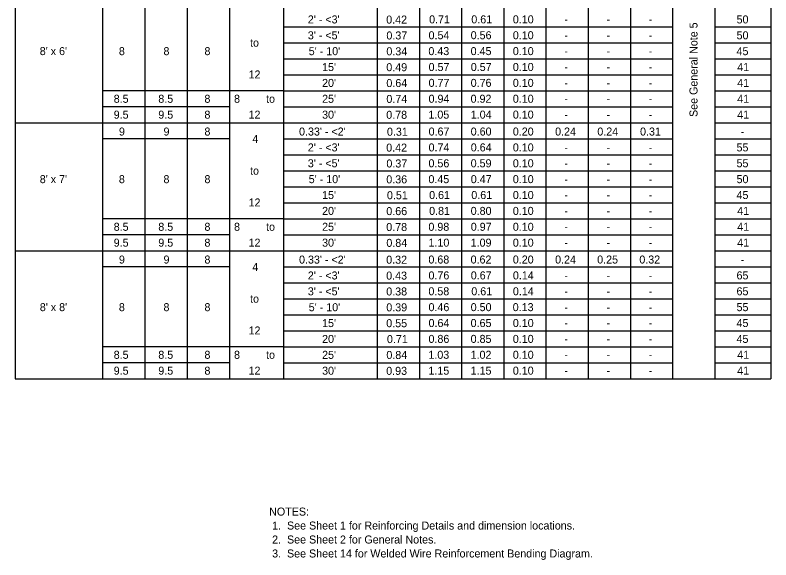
# Model space of a CAD drawing. Extents: x 10342.77 to 10344.98, y 76399.47 to 76400.59.
# Drawn here: x 10343.418 to 10344.012, y 76399.783 to 76400.212 of the extents above; entities that cross this region are included whole.
import ezdxf

# ---------------------------------------------------------------- set-up
doc = ezdxf.new("R2010")
doc.units = 0
doc.layers.add('AdhocPoint_dp', color=7, linetype='Continuous')
doc.layers.add('PlotBorder_dp', color=7, linetype='Continuous')

msp = doc.modelspace()

# ---------------------------------------------------------------- linework, layer by layer
at = {"layer": 'PlotBorder_dp'}
for p, q in [((10343.41763, 76400.49971), (10343.41763, 76399.92549)), ((10344.01237, 76400.49971), (10344.01237, 76399.92549)), ((10343.48627, 76400.47984), (10343.48627, 76399.92549)), ((10343.62871, 76400.47984), (10343.62871, 76399.92549)), ((10343.70259, 76400.47984), (10343.70259, 76399.92549)), ((10343.96818, 76400.47984), (10343.96818, 76399.92549)), ((10343.51963, 76400.46724), (10343.51963, 76399.92549)), ((10343.55299, 76400.46724), (10343.55299, 76399.92549)), ((10343.58635, 76400.46724), (10343.58635, 76399.92549)), ((10343.73579, 76400.44209), (10343.73579, 76399.92549)), ((10343.76899, 76400.44209), (10343.76899, 76399.92549)), ((10343.80219, 76400.44209), (10343.80219, 76399.92549)), ((10343.83539, 76400.44209), (10343.83539, 76399.92549)), ((10343.86859, 76400.44209), (10343.86859, 76399.92549)), ((10343.86859, 76400.44209), (10343.86859, 76399.92549)), ((10343.90178, 76400.44209), (10343.90178, 76399.92549)), ((10343.93498, 76400.44209), (10343.93498, 76399.92549)), ((10343.62871, 76400.20269), (10343.93498, 76400.20269)), ((10343.96818, 76400.20269), (10344.01237, 76400.20269)), ((10343.62871, 76400.19009), (10343.93498, 76400.19009)), ((10343.96818, 76400.19009), (10344.01237, 76400.19009)), ((10343.62871, 76400.17749), (10343.93498, 76400.17749)), ((10343.96818, 76400.17749), (10344.01237, 76400.17749)), ((10343.62871, 76400.16489), (10343.93498, 76400.16489)), ((10343.96818, 76400.16489), (10344.01237, 76400.16489)), ((10343.62871, 76400.15229), (10343.48627, 76400.15229)), ((10343.62871, 76400.15229), (10343.93498, 76400.15229)), ((10343.96818, 76400.15229), (10344.01237, 76400.15229)), ((10343.58635, 76400.13969), (10343.48627, 76400.13969)), ((10343.62871, 76400.13969), (10343.93498, 76400.13969)), ((10343.96818, 76400.13969), (10344.01237, 76400.13969)), ((10343.41763, 76400.12709), (10343.93498, 76400.12709)), ((10343.62931, 76400.12709), (10343.70148, 76400.12709)), ((10343.96818, 76400.12709), (10344.01237, 76400.12709)), ((10343.58635, 76400.11449), (10343.48627, 76400.11449)), ((10343.62871, 76400.11449), (10343.93498, 76400.11449)), ((10343.96818, 76400.11449), (10344.01237, 76400.11449)), ((10343.62871, 76400.10189), (10343.93498, 76400.10189)), ((10343.96818, 76400.10189), (10344.01237, 76400.10189)), ((10343.62871, 76400.08929), (10343.93498, 76400.08929)), ((10343.96818, 76400.08929), (10344.01237, 76400.08929)), ((10343.62871, 76400.07669), (10343.93498, 76400.07669)), ((10343.96818, 76400.07669), (10344.01237, 76400.07669)), ((10343.62871, 76400.06409), (10343.93498, 76400.06409)), ((10343.96818, 76400.06409), (10344.01237, 76400.06409)), ((10343.62871, 76400.05149), (10343.48627, 76400.05149)), ((10343.62871, 76400.05149), (10343.93498, 76400.05149)), ((10343.96818, 76400.05149), (10344.01237, 76400.05149)), ((10343.58635, 76400.03889), (10343.48627, 76400.03889)), ((10343.62871, 76400.03889), (10343.93498, 76400.03889)), ((10343.96818, 76400.03889), (10344.01237, 76400.03889)), ((10343.41763, 76400.02629), (10343.93498, 76400.02629)), ((10343.62931, 76400.02629), (10343.70148, 76400.02629)), ((10343.96818, 76400.02629), (10344.01237, 76400.02629)), ((10343.58635, 76400.01369), (10343.48627, 76400.01369)), ((10343.62871, 76400.01369), (10343.93498, 76400.01369)), ((10343.96818, 76400.01369), (10344.01237, 76400.01369)), ((10343.62871, 76400.00109), (10343.93498, 76400.00109)), ((10343.96818, 76400.00109), (10344.01237, 76400.00109)), ((10343.62871, 76399.98849), (10343.93498, 76399.98849)), ((10343.96818, 76399.98849), (10344.01237, 76399.98849)), ((10343.62871, 76399.97589), (10343.93498, 76399.97589)), ((10343.96818, 76399.97589), (10344.01237, 76399.97589)), ((10343.62871, 76399.96329), (10343.93498, 76399.96329)), ((10343.96818, 76399.96329), (10344.01237, 76399.96329)), ((10343.62871, 76399.95069), (10343.48627, 76399.95069)), ((10343.62871, 76399.95069), (10343.93498, 76399.95069)), ((10343.96818, 76399.95069), (10344.01237, 76399.95069)), ((10343.58635, 76399.93809), (10343.48627, 76399.93809)), ((10343.62871, 76399.93809), (10343.93498, 76399.93809)), ((10343.62931, 76399.93809), (10343.70148, 76399.93809)), ((10343.96818, 76399.93809), (10344.01237, 76399.93809)), ((10343.41763, 76399.92549), (10344.01237, 76399.92549))]:
    msp.add_line(p, q, dxfattribs=at)

# ---------------------------------------------------------------- texts
at = {"layer": 'AdhocPoint_dp'}
msp.add_text('See General Note 5', height=0.0063, rotation=90, dxfattribs=at).set_placement((10343.95463, 76400.13159))
at = {"layer": 'PlotBorder_dp'}
for s, p in [("2' - <3'", (10343.64797, 76400.20526)), ('0.42', (10343.70967, 76400.20515)), ('0.71', (10343.74343, 76400.20531)), ('0.61', (10343.77663, 76400.20531)), ('0.10', (10343.8093, 76400.20531)), ('50', (10343.98538, 76400.20526)), ('-', (10343.84986, 76400.20531)), ('-', (10343.88307, 76400.20531)), ('-', (10343.91625, 76400.20531)), ("3' - <5'", (10343.64797, 76400.19276)), ('0.37', (10343.70981, 76400.19265)), ('0.54', (10343.74299, 76400.19281)), ('0.56', (10343.77613, 76400.19281)), ('0.10', (10343.8093, 76400.19281)), ('50', (10343.98538, 76400.19276)), ('to', (10343.60251, 76400.18692)), ('-', (10343.84986, 76400.19281)), ('-', (10343.88307, 76400.19281)), ('-', (10343.91625, 76400.19281)), ("8' x 6'", (10343.43702, 76400.18031)), ('8', (10343.49929, 76400.18027)), ('8', (10343.53438, 76400.18027)), ('8', (10343.56662, 76400.18027)), ("5' - 10'", (10343.64868, 76400.18026)), ('0.34', (10343.70979, 76400.18015)), ('0.43', (10343.74286, 76400.18031)), ('0.45', (10343.77609, 76400.18031)), ('0.10', (10343.8093, 76400.18031)), ('45', (10343.98533, 76400.18026)), ('-', (10343.84986, 76400.18031)), ('-', (10343.88307, 76400.18031)), ('-', (10343.91625, 76400.18031)), ("15'", (10343.6592, 76400.16776)), ('0.49', (10343.70973, 76400.16765)), ('0.57', (10343.74301, 76400.16781)), ('0.57', (10343.77621, 76400.16781)), ('0.10', (10343.8093, 76400.16781)), ('41', (10343.98587, 76400.16776)), ('12', (10343.60134, 76400.16192)), ('-', (10343.84986, 76400.16781)), ('-', (10343.88307, 76400.16781)), ('-', (10343.91625, 76400.16781)), ("20'", (10343.6592, 76400.15526)), ('0.64', (10343.70979, 76400.15515)), ('0.77', (10343.74301, 76400.15531)), ('0.76', (10343.77613, 76400.15531)), ('0.10', (10343.8093, 76400.15531)), ('41', (10343.98587, 76400.15526)), ('-', (10343.84986, 76400.15531)), ('-', (10343.88307, 76400.15531)), ('-', (10343.91625, 76400.15531)), ('8.5', (10343.49522, 76400.14277)), ('8.5', (10343.53032, 76400.14277)), ('8', (10343.56662, 76400.14277)), ('8 ', (10343.58991, 76400.14277)), ('to', (10343.61511, 76400.14277)), ("25'", (10343.6592, 76400.14276)), ('0.74', (10343.70979, 76400.14265)), ('0.94', (10343.74299, 76400.14281)), ('0.92', (10343.77607, 76400.14281)), ('0.10', (10343.8093, 76400.14281)), ('-', (10343.84986, 76400.14281)), ('-', (10343.88307, 76400.14281)), ('-', (10343.91625, 76400.14281)), ('41', (10343.98587, 76400.14276)), ('9.5', (10343.49522, 76400.13027)), ('9.5', (10343.53032, 76400.13027)), ('8', (10343.56662, 76400.13027)), ('12', (10343.60134, 76400.13027)), ("30'", (10343.6592, 76400.13026)), ('0.78', (10343.70969, 76400.13015)), ('1.05', (10343.74289, 76400.13031)), ('1.04', (10343.77619, 76400.13031)), ('0.10', (10343.8093, 76400.13031)), ('-', (10343.84986, 76400.13031)), ('-', (10343.88307, 76400.13031)), ('-', (10343.91625, 76400.13031)), ('41', (10343.98587, 76400.13026)), ('9', (10343.49933, 76400.11697)), ('9', (10343.53443, 76400.11697)), ('8', (10343.56662, 76400.11697)), ("0.33' - <2'", (10343.64107, 76400.11698)), ('0.31', (10343.71024, 76400.11682)), ('0.67', (10343.74301, 76400.11698)), ('0.60', (10343.77615, 76400.11698)), ('0.20', (10343.8093, 76400.11698)), ('0.24', (10343.84258, 76400.11698)), ('0.24', (10343.87579, 76400.11698)), ('0.31', (10343.90942, 76400.11698)), ('4', (10343.60429, 76400.11112)), ('-', (10343.98864, 76400.11698)), ("2' - <3'", (10343.64797, 76400.10448)), ('0.42', (10343.70967, 76400.10432)), ('0.74', (10343.74299, 76400.10448)), ('0.64', (10343.77619, 76400.10448)), ('0.10', (10343.8093, 76400.10448)), ('55', (10343.98533, 76400.10448)), ('-', (10343.84986, 76400.10448)), ('-', (10343.88307, 76400.10448)), ('-', (10343.91625, 76400.10448)), ("3' - <5'", (10343.64797, 76400.09198)), ('0.37', (10343.70981, 76400.09182)), ('0.56', (10343.74293, 76400.09198)), ('0.59', (10343.77613, 76400.09198)), ('0.10', (10343.8093, 76400.09198)), ('55', (10343.98533, 76400.09198)), ('to', (10343.60251, 76400.08612)), ('-', (10343.84986, 76400.09198)), ('-', (10343.88307, 76400.09198)), ('-', (10343.91625, 76400.09198)), ("8' x 7'", (10343.43702, 76400.07948)), ('8', (10343.49929, 76400.07947)), ('8', (10343.53438, 76400.07947)), ('8', (10343.56662, 76400.07947)), ("5' - 10'", (10343.64868, 76400.07948)), ('0.36', (10343.70973, 76400.07932)), ('0.45', (10343.74289, 76400.07948)), ('0.47', (10343.77621, 76400.07948)), ('0.10', (10343.8093, 76400.07948)), ('50', (10343.98538, 76400.07948)), ('-', (10343.84986, 76400.07948)), ('-', (10343.88307, 76400.07948)), ('-', (10343.91625, 76400.07948)), ("15'", (10343.6592, 76400.06698)), ('0.51', (10343.71024, 76400.06682)), ('0.61', (10343.74343, 76400.06698)), ('0.61', (10343.77663, 76400.06698)), ('0.10', (10343.8093, 76400.06698)), ('45', (10343.98533, 76400.06698)), ('12', (10343.60134, 76400.06112)), ('-', (10343.84986, 76400.06698)), ('-', (10343.88307, 76400.06698)), ('-', (10343.91625, 76400.06698)), ("20'", (10343.6592, 76400.05448)), ('0.66', (10343.70973, 76400.05432)), ('0.81', (10343.74343, 76400.05448)), ('0.80', (10343.77615, 76400.05448)), ('0.10', (10343.8093, 76400.05448)), ('41', (10343.98587, 76400.05448)), ('-', (10343.84986, 76400.05448)), ('-', (10343.88307, 76400.05448)), ('-', (10343.91625, 76400.05448)), ('8.5', (10343.49522, 76400.04197)), ('8.5', (10343.53032, 76400.04197)), ('8', (10343.56662, 76400.04197)), ('8 ', (10343.58991, 76400.04197)), ('to', (10343.61511, 76400.04197)), ("25'", (10343.6592, 76400.04198)), ('0.78', (10343.70969, 76400.04182)), ('0.98', (10343.74288, 76400.04198)), ('0.97', (10343.77621, 76400.04198)), ('0.10', (10343.8093, 76400.04198)), ('-', (10343.84986, 76400.04198)), ('-', (10343.88307, 76400.04198)), ('-', (10343.91625, 76400.04198)), ('41', (10343.98587, 76400.04198)), ('9.5', (10343.49522, 76400.02947)), ('9.5', (10343.53032, 76400.02947)), ('8', (10343.56662, 76400.02947)), ('12', (10343.60134, 76400.02947)), ("30'", (10343.6592, 76400.02948)), ('0.84', (10343.70979, 76400.02932)), ('1.10', (10343.74294, 76400.02948)), ('1.09', (10343.77613, 76400.02948)), ('0.10', (10343.8093, 76400.02948)), ('-', (10343.84986, 76400.02948)), ('-', (10343.88307, 76400.02948)), ('-', (10343.91625, 76400.02948)), ('41', (10343.98587, 76400.02948)), ('9', (10343.49933, 76400.01617)), ('9', (10343.53443, 76400.01617)), ('8', (10343.56662, 76400.01617)), ("0.33' - <2'", (10343.64107, 76400.01614)), ('0.32', (10343.70967, 76400.01604)), ('0.68', (10343.74288, 76400.01619)), ('0.62', (10343.77607, 76400.01619)), ('0.20', (10343.8093, 76400.01619)), ('0.24', (10343.84258, 76400.01619)), ('0.25', (10343.87569, 76400.01619)), ('0.32', (10343.90885, 76400.01619)), ('-', (10343.98864, 76400.01619)), ('4', (10343.60429, 76400.01032)), ("2' - <3'", (10343.64797, 76400.00364)), ('0.43', (10343.70966, 76400.00354)), ('0.76', (10343.74293, 76400.00369)), ('0.67', (10343.77621, 76400.00369)), ('0.14', (10343.80935, 76400.00369)), ('65', (10343.98533, 76400.00369)), ('-', (10343.84986, 76400.00369)), ('-', (10343.88307, 76400.00369)), ('-', (10343.91625, 76400.00369)), ("3' - <5'", (10343.64797, 76399.99114)), ('0.38', (10343.70969, 76399.99104)), ('0.58', (10343.74288, 76399.99119)), ('0.61', (10343.77663, 76399.99119)), ('0.14', (10343.80935, 76399.99119)), ('65', (10343.98533, 76399.99119)), ('to', (10343.60251, 76399.98532)), ('-', (10343.84986, 76399.99119)), ('-', (10343.88307, 76399.99119)), ('-', (10343.91625, 76399.99119)), ("8' x 8'", (10343.43707, 76399.97869)), ('8', (10343.49929, 76399.97867)), ('8', (10343.53438, 76399.97867)), ('8', (10343.56662, 76399.97867)), ("5' - 10'", (10343.64868, 76399.97864)), ('0.39', (10343.70973, 76399.97854)), ('0.46', (10343.74293, 76399.97869)), ('0.50', (10343.77615, 76399.97869)), ('0.13', (10343.80922, 76399.97869)), ('55', (10343.98533, 76399.97869)), ('-', (10343.84986, 76399.97869)), ('-', (10343.88307, 76399.97869)), ('-', (10343.91625, 76399.97869)), ("15'", (10343.6592, 76399.96614)), ('0.55', (10343.70969, 76399.96604)), ('0.64', (10343.74299, 76399.96619)), ('0.65', (10343.77609, 76399.96619)), ('0.10', (10343.8093, 76399.96619)), ('45', (10343.98533, 76399.96619)), ('12', (10343.60134, 76399.96032)), ('-', (10343.84986, 76399.96619)), ('-', (10343.88307, 76399.96619)), ('-', (10343.91625, 76399.96619)), ("20'", (10343.6592, 76399.95364)), ('0.71', (10343.71024, 76399.95354)), ('0.86', (10343.74293, 76399.95369)), ('0.85', (10343.77609, 76399.95369)), ('0.10', (10343.8093, 76399.95369)), ('45', (10343.98533, 76399.95369)), ('-', (10343.84986, 76399.95369)), ('-', (10343.88307, 76399.95369)), ('-', (10343.91625, 76399.95369)), ('8.5', (10343.49522, 76399.94117)), ('8.5', (10343.53032, 76399.94117)), ('8', (10343.56662, 76399.94117)), ('8 ', (10343.58991, 76399.94117)), ("25'", (10343.6592, 76399.94114)), ('0.84', (10343.70979, 76399.94104)), ('1.03', (10343.74286, 76399.94119)), ('1.02', (10343.77607, 76399.94119)), ('0.10', (10343.8093, 76399.94119)), ('41', (10343.98587, 76399.94119)), ('to', (10343.61511, 76399.94117)), ('-', (10343.84986, 76399.94119)), ('-', (10343.88307, 76399.94119)), ('-', (10343.91625, 76399.94119)), ('9.5', (10343.49522, 76399.92867)), ('9.5', (10343.53032, 76399.92867)), ('8', (10343.56662, 76399.92867)), ('12', (10343.60134, 76399.92867)), ("30'", (10343.6592, 76399.92864)), ('0.93', (10343.70966, 76399.92854)), ('1.15', (10343.74289, 76399.92869)), ('1.15', (10343.77609, 76399.92869)), ('0.10', (10343.8093, 76399.92869)), ('-', (10343.84986, 76399.92869)), ('-', (10343.88307, 76399.92869)), ('-', (10343.91625, 76399.92869)), ('41', (10343.98587, 76399.92869)), ('NOTES:', (10343.61754, 76399.81771)), (' 1.  See Sheet 1 for Reinforcing Details and dimension locations.', (10343.61754, 76399.80671)), (' 2.  See Sheet 2 for General Notes.', (10343.61754, 76399.79571)), (' 3.  See Sheet 14 for Welded Wire Reinforcement Bending Diagram.', (10343.61754, 76399.78471))]:
    msp.add_text(s, height=0.0063, dxfattribs=at).set_placement(p)

doc.saveas('drawing.dxf')
